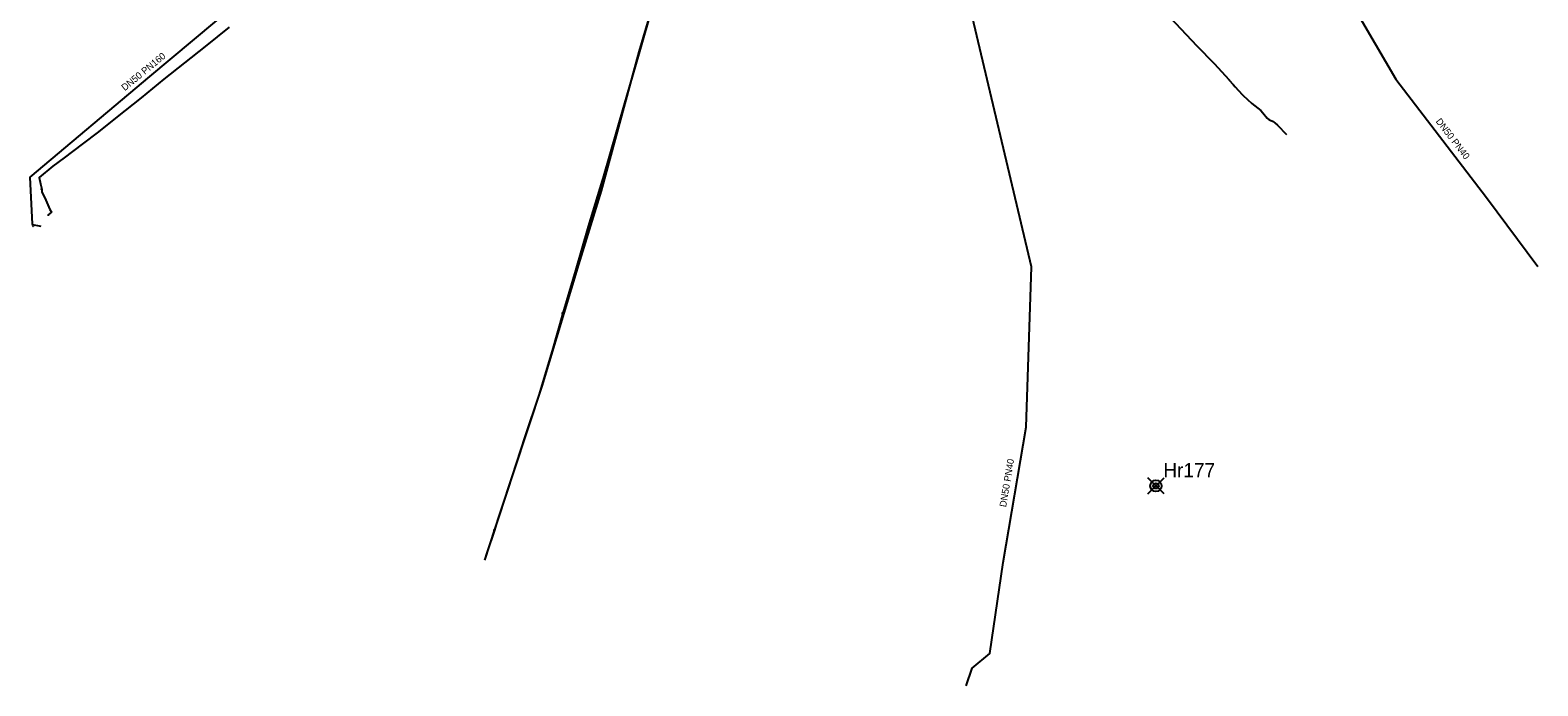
# Model space of a CAD drawing. Extents: x -576799 to -569298, y -1206368 to -1203382.
# Drawn here: x -575221 to -573894, y -1206368 to -1205791 of the extents above; entities that cross this region are included whole.
import ezdxf

# ---------------------------------------------------------------- set-up
doc = ezdxf.new("R2010")
doc.units = 0
for name, color, linetype in [('12', 7, 'Continuous'), ('14', 7, 'Continuous'), ('Vrstva 10', 7, 'Continuous'), ('Vrstva 2', 7, 'Continuous'), ('Vrstva 26', 7, 'Continuous'), ('Vrstva 31', 7, 'Continuous'), ('Vrstva 33', 7, 'Continuous'), ('Vrstva 35', 7, 'Continuous'), ('Vrstva 50', 7, 'Continuous'), ('Vrstva 56', 7, 'Continuous'), ('Vrstva 9', 7, 'Continuous')]:
    doc.layers.add(name, color=color, linetype=linetype)

msp = doc.modelspace()

# ---------------------------------------------------------------- linework, layer by layer
at = {"layer": '12'}
msp.add_lwpolyline([(-575046.2, -1205788.2), (-575067.3, -1205805.3), (-575085.6, -1205819.7), (-575103.8, -1205834.1), (-575123.6, -1205850.4), (-575144.9, -1205867.1), (-575161.2, -1205880.4), (-575175.6, -1205891.2), (-575191.3, -1205903.2), (-575201.4, -1205910.7), (-575213.5, -1205920.6), (-575212.3, -1205926.3), (-575211.2, -1205930.9), (-575211.2, -1205933.4), (-575208.6, -1205938.6), (-575204.2, -1205948.6), (-575202.6, -1205951.1), (-575205.4, -1205953.4), (-575205.5, -1205954.2)], dxfattribs=at)
at = {"layer": '14'}
msp.add_lwpolyline([(-574227.3, -1205769.7), (-574194.5, -1205804.7), (-574179.4, -1205820.4), (-574166.2, -1205834.8), (-574166.2, -1205835), (-574162.6, -1205838.8), (-574160.8, -1205840.8), (-574154.7, -1205847.5), (-574153.8, -1205848.4), (-574146.2, -1205855.5), (-574143.5, -1205857.6), (-574138.2, -1205861.7), (-574136.4, -1205863.8), (-574132.5, -1205868.3), (-574131, -1205869.9), (-574127, -1205871.4), (-574125.8, -1205872.5), (-574123.5, -1205874.6), (-574115.5, -1205882.8)], dxfattribs=at)
at = {"layer": 'Vrstva 10'}
for radius in [5, 2.4]:
    msp.add_circle((-574230.5, -1206191.9), radius, dxfattribs=at)
at = {"layer": 'Vrstva 26'}
for p, q in [((-574237.6, -1206199), (-574223.4, -1206184.8)), ((-574223.4, -1206199), (-574237.6, -1206184.8))]:
    msp.add_line(p, q, dxfattribs=at)
at = {"layer": 'Vrstva 31'}
msp.add_lwpolyline([(-574640.2, -1205653.2), (-574641.1, -1205656.7), (-574649.1, -1205685.1), (-574658.3, -1205717.9), (-574674.1, -1205772), (-574685.7, -1205811.9), (-574698.8, -1205857.2), (-574717.4, -1205921.4), (-574717.8, -1205923.1), (-574730.2, -1205963.8), (-574741.4, -1206002.3), (-574752.6, -1206040), (-574761.9, -1206073.2), (-574773.7, -1206112.2), (-574785.7, -1206147.9), (-574801.2, -1206195.8), (-574810.9, -1206225), (-574812.8, -1206230.9), (-574819.3, -1206250.7), (-574821.5, -1206257.3)], dxfattribs=at)
at = {"layer": 'Vrstva 33'}
msp.add_line((-575219.1, -1205962.8), (-575219.3, -1205961.7), dxfattribs=at)
for points in [[(-575219.3, -1205961.7), (-575221.4, -1205920.2), (-575115.9, -1205831.7), (-574999.9, -1205734.4), (-574889.4, -1205643.5), (-574714.4, -1205502.2), (-574581.2, -1205391.4)], [(-574397.6, -1206367.8), (-574392.2, -1206352.3), (-574376.7, -1206339.5), (-574364.9, -1206259.2), (-574344.8, -1206140.3), (-574339.9, -1205999.2), (-574397.2, -1205757.1), (-574420.5, -1205688.1), (-574438.6, -1205639.8), (-574526.9, -1205475), (-574580.1, -1205417.3)], [(-574640.3, -1205653.3), (-574646.5, -1205677), (-574669.4, -1205755.1), (-574685.6, -1205810), (-574718.7, -1205932.2), (-574738.8, -1205997), (-574771.1, -1206104.2), (-574808.3, -1206216.9), (-574821.6, -1206257.3)], [(-575211.6, -1205963.7), (-575213.2, -1205963.4), (-575219.2, -1205962.2)]]:
    msp.add_lwpolyline(points, dxfattribs=at)
at = {"layer": 'Vrstva 35'}
msp.add_lwpolyline([(-574077.7, -1205753.9), (-574066.8, -1205752.6), (-574019.5, -1205834.1), (-573939.7, -1205938.1), (-573894.4, -1205999)], dxfattribs=at)
at = {"layer": 'Vrstva 50'}
for p, q in [((-575219.2, -1205962.8), (-575219.3, -1205962.7)), ((-575219, -1205962.8), (-575219.2, -1205962.8)), ((-575219.1, -1205963.5), (-575218.8, -1205963.5)), ((-575219.1, -1205963.5), (-575219.1, -1205963.7)), ((-575219, -1205962.8), (-575219, -1205962.6)), ((-575218.8, -1205963.5), (-575218.8, -1205963.6))]:
    msp.add_line(p, q, dxfattribs=at)
msp.add_lwpolyline([(-575211.2, -1205930.7), (-575211.1, -1205931.1), (-575211.3, -1205931.1), (-575211.4, -1205930.7)], close=True, dxfattribs=at)
for points in [[(-574752.8, -1206040.7), (-574752.8, -1206039.9), (-574752.4, -1206039.3), (-574752.4, -1206040.1), (-574752.8, -1206040.7)], [(-574813.1, -1206231.6), (-574813, -1206230.8), (-574812.6, -1206230.2), (-574812.7, -1206231), (-574813.1, -1206231.6)]]:
    msp.add_lwpolyline(points, dxfattribs=at)

# ---------------------------------------------------------------- texts
at = {"layer": 'Vrstva 2'}
msp.add_text('Hr177', height=12.5, dxfattribs=at).set_placement((-574224, -1206184.4))
at = {"layer": 'Vrstva 56'}
msp.add_text('CH', height=0.3, rotation=74.5343, dxfattribs=at).set_placement((-574718, -1205922.4))
at = {"layer": 'Vrstva 9'}
for s, rotation, p in [('DN50 PN160', 39.2131, (-575138.1, -1205844.7)), ('DN50 PN40', 307.482, (-573984.6, -1205871.3)), ('DN50 PN40', 80.4071, (-574362.4, -1206210.9))]:
    msp.add_text(s, height=6, rotation=rotation, dxfattribs=at).set_placement(p)

doc.saveas('drawing.dxf')
